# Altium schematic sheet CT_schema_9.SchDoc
size 226 x 144 mm
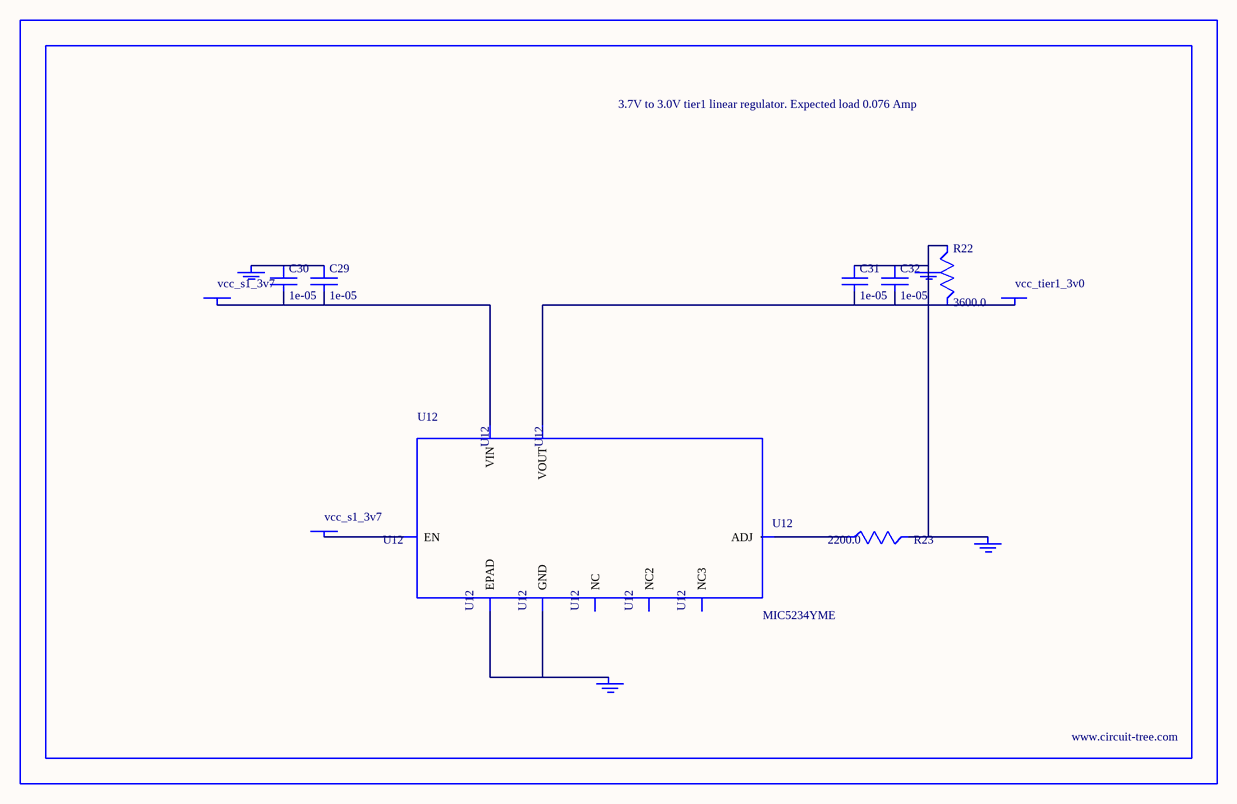
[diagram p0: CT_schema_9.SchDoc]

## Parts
BORDER8  (no value)
C29  1e-05  [C1210]
C30  1e-05  [C1210]
C31  1e-05  [C1210]
C32  1e-05  [C1210]
GND_INSTANCE_8_0  (no value)
GND_INSTANCE_8_1  (no value)
GND_INSTANCE_8_2  (no value)
GND_INSTANCE_8_3  (no value)
POWER_INSTANCE_8_0  vcc_tier1_3v0
POWER_INSTANCE_8_1  vcc_s1_3v7
POWER_INSTANCE_8_2  vcc_s1_3v7
R22  3600.0  [R0603]
R23  2200.0  [R0603]
U12  MIC5234YME  [SOIC-8_EP]

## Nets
NetC29_1: C29.1 C30.1 GND_INSTANCE_8_3.0(GND)
NetC29_2: C29.2 C30.2 POWER_INSTANCE_8_2.0(PWR) U12.8(VIN)
NetC31_1: C31.1 C32.1 GND_INSTANCE_8_0.0(GND) GND_INSTANCE_8_1.0(GND) R22.1 R23.2
NetC31_2: C31.2 C32.2 POWER_INSTANCE_8_0.0(PWR) R22.2 U12.1(VOUT)
NetGND_INSTANCE_8_2_0: GND_INSTANCE_8_2.0(GND) U12.7(GND) U12.EPAD
NetPOWER_INSTANCE_8_1_0: POWER_INSTANCE_8_1.0(PWR) U12.5(EN)
NetR23_1: R23.1 U12.4(ADJ)

Not connected (* = marked no-connect by the designer): U12 2(NC) 3(NC2) 6(NC3)

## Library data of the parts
BORDER8 = BORDER_PAGE8
C29-C32 = C1210C106K5PACTU
GND_INSTANCE_8_0-GND_INSTANCE_8_3 = GND
POWER_INSTANCE_8_0-POWER_INSTANCE_8_2 = PWR
R22 = RC0603JR-073K6L
R23 = RC0603JR-072K2L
